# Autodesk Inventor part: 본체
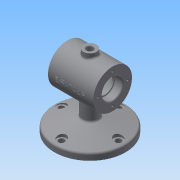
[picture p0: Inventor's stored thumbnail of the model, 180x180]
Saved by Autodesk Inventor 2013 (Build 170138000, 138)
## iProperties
Created: 2018-12
Part Number: 본체
Material: 일반
Document SubType Name: Modeling
Designer: Gpr
Density: 1 g/cm^3
Mass: 245.298 g
Surface Area: 551.018 cm^2
Volume: 245.298 cm^3
Author: Gpr
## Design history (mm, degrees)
sketch "스케치1"
  geometry: C1 r 55 at (0, 0); 1 further point
  constraints: 1 centre point, 1 coincident
  dimensions: "d0" = 110 diameter of C1
extrude "돌출1" new body sketch "스케치1" distance "d1" = 10; taper "d2" = 0 deg
sketch "스케치2"
  geometry: L1 (-35, 105)-(35, 105); L2 (35, 105)-(35, 91); L3 (35, 91)-(23, 91); L4 (23, 91)-(23, 89); L5 (23, 89)-(20, 89); L6 (20, 89)-(20, 100); L7 (20, 100)-(-20, 100); L8 (-20, 100)-(-20, 89); L9 (-20, 89)-(-23, 89); L10 (-23, 89)-(-23, 91); L11 (-23, 91)-(-35, 91); L12 (-35, 91)-(-35, 105); L13 (-35, 75)-(35, 75); 4 further points
  constraints: 26 end point, 7 horizontal, 6 vertical, 5 vertical alignment, 3 midpoint, 2 horizontal alignment
  dimensions: "d3" = 28 diameter of L9 L13; "d5" = 32 diameter of L11 L13; "d6" = 50 diameter of L7 L13; "d7" = 40 distance of L6.end L7.end; "d8" = 3 distance of L8.end L9.end; "d9" = 12 distance of L10.end L11.end; "d10" = 12 distance of L2.end L3.end; "d11" = 75 distance of point (0, 0) point (0, 75); "d12" = 60 diameter of L1 L13
revolve "회전1" sketch "스케치2" stored, may be unused: angle "d13" = 90 deg
sketch "스케치6"
  geometry: C1 r 12 at (0, 0); 1 further point
  constraints: 1 centre point, 1 coincident
  dimensions: "d14" = 24 diameter of C1
extrude "돌출2" join sketch "스케치6" stored distance "d15" = 15; taper "d16" = 0 deg
sketch "스케치7"
  geometry: C1 r 55 at (0, 0) reference; 1 further point
extrude "돌출3" join sketch "스케치7" distance "d17" = 15; taper "d18" = -75 deg
sketch "스케치8"
  geometry: C1 r 30 at (0, 0) reference; 2 further points
  constraints: 1 vertical alignment
  dimensions: "d19" = 23 distance of C1.centre point (0, 23)
hole "구멍1" sketch "스케치8" at (0, 23) diameter "d20" = 3.242; stored, may be unused: countersink angle "d24" = 90 deg, drill point angle "d26" = 118 deg; dims "d21" = 8, "d22" = 4, "d23" = 2, "d25" = 10
fillet "모깎기1" dims "d30" = 0.3
chamfer "모따기1" distance "d31" = 1; stored, may be unused: second distance "d32" = 2, angle "d33" = 45 deg
node "작업 평면1"
sketch "스케치9"
  geometry: C1 r 10 at (0, 0); 1 further point
  constraints: 1 centre point, 1 coincident
  dimensions: "d35" = 20 diameter of C1
extrude "돌출4" join sketch "스케치9" stored distance "d36" = 15; taper "d37" = 0 deg
hole "구멍2" diameter "d40" = 10; stored, may be unused: countersink angle "d44" = 90 deg, drill point angle "d46" = 0 deg; dims "d38" = 10, "d39" = 10, "d41" = 8, "d42" = 4, "d43" = 2, "d45" = 10
chamfer "모따기2" distance "d47" = 1; stored, may be unused: second distance "d48" = 2, angle "d49" = 45 deg
sketch "스케치10"
  geometry: 2 further points
  constraints: 1 vertical alignment
  dimensions: "d50" = 44 distance of point (0, 0) point (0, 44)
hole "구멍3" sketch "스케치10" at (0, 44) diameter "d51" = 9; stored, may be unused: countersink angle "d55" = 90 deg, drill point angle "d57" = 0 deg; dims "d52" = 8, "d53" = 4, "d54" = 2, "d56" = 10
hole "구멍4" diameter "d60" = 14; stored, may be unused: countersink angle "d64" = 90 deg, drill point angle "d66" = 0 deg; dims "d58" = 10, "d59" = 10, "d61" = 8, "d62" = 4, "d63" = 2, "d65" = 10
node "작업 평면2"
sketch "스케치11"
  geometry: L1 (-35, 45)-(-35, 105) reference; L2 (-35, 105)-(35, 105) reference; 2 further points
  constraints: 1 other
  dimensions: "d71" = 35 distance from line of point (0, 75) L1; "d73" = 30 distance from line of point (0, 75) L2
feature "엠보싱1" sketch "스케치11" dims "d74" = 0.5, "d75" = 0
fillet "모깎기2" dims "d76" = 3
node "솔리드1"
pattern_circular "원형 패턴1" dims angle "d28" = 360 deg
mirror "대칭1"
pattern_circular "원형 패턴2" dims angle "d68" = 360 deg
other parameters: "d34" = -112, "d70" = 71.75
